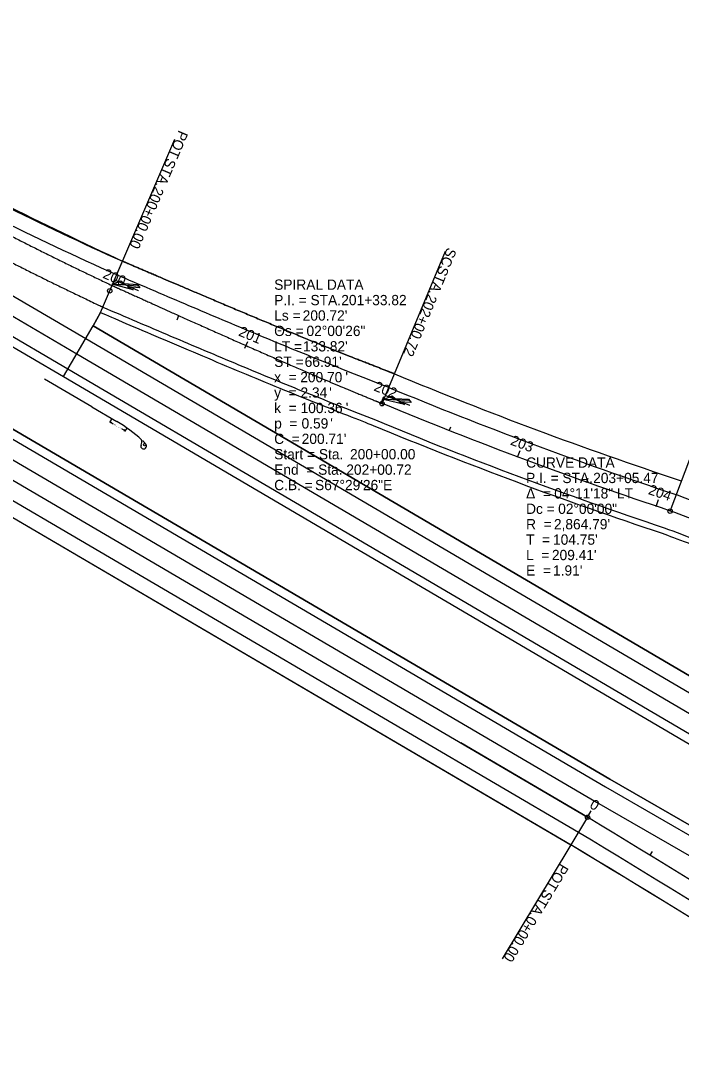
# Model space of a CAD drawing. Extents: x 76539 to 88870, y 518807 to 527554.
# Drawn here: x 85984 to 86434, y 523086 to 523783 of the extents above; entities that cross this region are included whole.
import ezdxf

# ---------------------------------------------------------------- set-up
doc = ezdxf.new("R2010")
doc.units = 0
for name, color, linetype in [('Default', 7, 'Continuous'), ('GE_P_Alignment_100_Cardinal_Points', 7, 'Continuous'), ('GE_P_Alignment_100_Curve_Data', 7, 'Continuous'), ('GE_P_Alignment_100_Stations', 7, 'Continuous'), ('PM_P_Cells', 7, 'Continuous'), ('PM_P_Channelizing_Line', 7, 'Continuous'), ('PM_P_Dotted_Line', 7, 'Continuous'), ('PM_P_Edge_Line', 7, 'Continuous'), ('PM_P_Lane_Line', 7, 'Continuous'), ('PV_P_Shoulder', 7, 'Continuous'), ('RD_P_GR_Lt', 7, 'Continuous'), ('RD_P_GR_Rt', 7, 'Continuous'), ('SC_Scratch1', 7, 'Continuous'), ('XS_P_Pavt_Surface', 7, 'Continuous')]:
    doc.layers.add(name, color=color, linetype=linetype)

msp = doc.modelspace()

# ---------------------------------------------------------------- linework, layer by layer
at = {"layer": 'Default'}
for points, degree in [([(86053.64, 523619.35), (86062.12, 523615.72), (86093.34, 523602.34), (86145.72, 523580.15), (86198.2, 523558.5), (86229.8, 523546.18), (86238.39, 523542.79)], 2), ([(86049.7, 523610.16), (86065.07, 523603.58), (86095.79, 523590.43), (86141.94, 523570.92), (86188.18, 523551.78), (86219.22, 523539.58), (86234.73, 523533.48)], 3), ([(86038.68, 523584.42), (86047.19, 523580.78), (86078.53, 523567.34), (86131.15, 523545.05), (86184, 523523.25), (86215.78, 523510.87), (86224.39, 523507.46)], 3), ([(86430.77, 523460.3), (86446.36, 523454.43), (86477.52, 523442.7), (86524.32, 523425.33), (86571.2, 523408.33), (86602.64, 523397.56), (86618.35, 523392.18)], 3), ([(86426.66, 523449.38), (86442.25, 523443.51), (86473.45, 523431.77), (86520.32, 523414.37), (86567.33, 523397.33), (86598.86, 523386.52), (86614.62, 523381.12)], 3), ([(86421.2, 523433.99), (86429.83, 523430.74), (86461.56, 523418.78), (86514.82, 523398.96), (86568.35, 523379.62), (86600.51, 523368.71), (86609.22, 523365.71)], 3)]:
    msp.add_open_spline(points, degree=degree, dxfattribs=at)
at = {"layer": 'GE_P_Alignment_100_Cardinal_Points'}
for p, q in [((86044.98, 523599.13), (86089.26, 523702.55)), ((86230.4, 523522.29), (86273.56, 523626.18)), ((86426.54, 523449.07), (86466.17, 523554.36)), ((86370.31, 523240.55), (86312.24, 523144.2))]:
    msp.add_line(p, q, dxfattribs=at)
for centre in [(86044.98, 523599.13), (86230.4, 523522.29), (86426.54, 523449.07), (86370.31, 523240.55)]:
    msp.add_circle(centre, 1.5, dxfattribs=at)
at = {"layer": 'GE_P_Alignment_100_Stations'}
for p, q in [((86044.98, 523599.13), (86046.95, 523603.73)), ((86090.96, 523579.48), (86092.13, 523582.24)), ((86137.02, 523560.04), (86138.95, 523564.65)), ((86183.25, 523540.99), (86184.38, 523543.77)), ((86229.72, 523522.55), (86231.53, 523527.21)), ((86276.06, 523503.77), (86277.17, 523506.56)), ((86322.72, 523485.79), (86324.47, 523490.47)), ((86369.68, 523468.63), (86370.68, 523471.45)), ((86416.93, 523452.28), (86418.52, 523457.02)), ((86370.31, 523240.55), (86372.89, 523244.84)), ((86413.06, 523214.62), (86414.62, 523217.19))]:
    msp.add_line(p, q, dxfattribs=at)
at = {"layer": 'PM_P_Cells'}
for p, q in [((86046.68, 523603.73), (86052.62, 523606.03)), ((86061, 523599.77), (86046.68, 523603.73)), ((86064.05, 523602.43), (86047.22, 523603.69)), ((86047.95, 523606.53), (86047.95, 523606.53)), ((86064.5, 523599.06), (86047.95, 523606.53)), ((86052.62, 523606.03), (86054.79, 523604.18)), ((86054.79, 523604.18), (86063.8, 523603.48)), ((86063.8, 523603.48), (86065.45, 523601.18)), ((86055.64, 523603.06), (86055.64, 523603.06)), ((86065.45, 523601.18), (86057.15, 523601.83)), ((86057.15, 523601.83), (86061, 523599.77)), ((86064.5, 523599.06), (86064.5, 523599.06)), ((86231.34, 523525.07), (86237.19, 523527.57)), ((86232.5, 523527.91), (86232.5, 523527.91)), ((86249.3, 523521.01), (86232.5, 523527.91)), ((86237.19, 523527.57), (86239.42, 523525.8)), ((86245.78, 523521.6), (86231.34, 523525.07)), ((86248.74, 523524.36), (86231.88, 523525.05)), ((86239.42, 523525.8), (86248.45, 523525.4)), ((86240.31, 523524.7), (86240.31, 523524.7)), ((86250.18, 523523.16), (86241.86, 523523.53)), ((86241.86, 523523.53), (86245.78, 523521.6)), ((86248.45, 523525.4), (86250.18, 523523.16)), ((86249.3, 523521.01), (86249.3, 523521.01))]:
    msp.add_line(p, q, dxfattribs=at)
at = {"layer": 'PM_P_Channelizing_Line'}
for p, q in [((85682.48, 523769.61), (86028.63, 523566.62)), ((86039.58, 523588.4), (86039.64, 523588.38)), ((86039.64, 523588.38), (86039.97, 523588.23)), ((86370.31, 523240.55), (86284.05, 523291.16))]:
    msp.add_line(p, q, dxfattribs=at)
msp.add_arc((81834.27, 515713.3), 8788.35, 54.569749, 58.926203, dxfattribs=at)
for points, degree in [([(85874.65, 523673.93), (85876.18, 523673.07), (85881.46, 523670.08), (85891.13, 523664.67), (85898.83, 523660.4), (85907.09, 523655.86), (85915.22, 523651.42), (85923.41, 523647), (85931.61, 523642.62), (85939.82, 523638.26), (85948.05, 523633.93), (85956.29, 523629.64), (85964.55, 523625.37), (85972.83, 523621.14), (85981.12, 523616.94), (85989.43, 523612.77), (85997.76, 523608.62), (86006.06, 523604.53), (86014.54, 523600.39), (86022.46, 523596.56), (86032.5, 523591.75), (86038, 523589.15), (86039.58, 523588.4)], 3), ([(86039.97, 523588.23), (86039.99, 523588.22), (86040.04, 523588.19), (86040.18, 523588.13), (86040.23, 523588.11), (86040.25, 523588.1)], 2)]:
    msp.add_open_spline(points, degree=degree, dxfattribs=at)
at = {"layer": 'PM_P_Dotted_Line'}
for p, q in [((84442.53, 524371.56), (86370.31, 523240.55)), ((86230.2, 523522.41), (86230.4, 523522.31)), ((86230.35, 523522.34), (86230.52, 523522.27))]:
    msp.add_line(p, q, dxfattribs=at)
for points, degree in [([(85882.47, 523687.88), (85885.15, 523686.36), (85890.51, 523683.33), (85898.56, 523678.82), (85906.63, 523674.35), (85914.72, 523669.9), (85922.83, 523665.48), (85930.95, 523661.09), (85939.1, 523656.73), (85947.25, 523652.4), (85955.43, 523648.1), (85963.62, 523643.84), (85971.83, 523639.6), (85980.05, 523635.39), (85988.29, 523631.21), (85996.55, 523627.07), (86004.82, 523622.95), (86013.11, 523618.87), (86021.41, 523614.81), (86029.73, 523610.79), (86038.06, 523606.79), (86043.63, 523604.16), (86046.42, 523602.84)], 3), ([(86046.54, 523602.78), (86054.95, 523598.99), (86085.93, 523584.97), (86137.96, 523561.72), (86190.34, 523538.89), (86221.85, 523525.9), (86230.35, 523522.34)], 2), ([(86230.4, 523522.31), (86230.42, 523522.31), (86230.46, 523522.29), (86230.52, 523522.26), (86230.57, 523522.24), (86230.63, 523522.21), (86230.69, 523522.19), (86230.74, 523522.16), (86230.8, 523522.14), (86230.86, 523522.12), (86230.91, 523522.09), (86230.97, 523522.07), (86231.03, 523522.04), (86231.08, 523522.02), (86231.14, 523521.99), (86231.2, 523521.97), (86231.25, 523521.94), (86231.31, 523521.92), (86231.37, 523521.89), (86231.42, 523521.87), (86231.48, 523521.84), (86231.52, 523521.83), (86231.54, 523521.82)], 3)]:
    msp.add_open_spline(points, degree=degree, dxfattribs=at)
at = {"layer": 'PM_P_Edge_Line'}
for p, q in [((84485.07, 524443.99), (86016.49, 523545.92)), ((84454.69, 524392.25), (86382.45, 523261.25)), ((84522.68, 524310.56), (86364.11, 523230.28)), ((86028.65, 523566.61), (87281.21, 522830.81)), ((86016.49, 523545.92), (87269.05, 522810.12)), ((86234.73, 523533.48), (86234.9, 523533.41)), ((86234.73, 523533.48), (86234.9, 523533.41)), ((86234.9, 523533.41), (86235, 523533.37)), ((86234.9, 523533.41), (86235, 523533.37)), ((86430.32, 523460.46), (86430.54, 523460.39)), ((86430.32, 523460.46), (86430.54, 523460.39)), ((86430.54, 523460.39), (86430.77, 523460.3)), ((86430.54, 523460.39), (86430.77, 523460.3)), ((86382.45, 523261.25), (86660.77, 523100.7))]:
    msp.add_line(p, q, dxfattribs=at)
for centre, radius, start, end in [((87059.11, 525861.34), 2467.13, 241.57045, 245.84895), ((87329.68, 526167.78), 2852.79, 247.43551, 251.62371), ((87329.68, 526167.78), 2852.79, 247.43551, 251.62371), ((87329.68, 526167.78), 2876.79, 247.43766, 251.61901), ((81834.27, 515713.3), 8776.35, 54.569749, 58.926203)]:
    msp.add_arc(centre, radius, start, end, dxfattribs=at)
for points in [[(86049.7, 523610.16), (86065.07, 523603.58), (86095.79, 523590.43), (86141.94, 523570.92), (86188.18, 523551.78), (86219.22, 523539.58), (86234.73, 523533.48)], [(86040.25, 523588.1), (86055.64, 523581.51), (86086.42, 523568.33), (86132.72, 523548.76), (86179.15, 523529.54), (86210.32, 523517.29), (86225.89, 523511.17)], [(86430.77, 523460.3), (86446.36, 523454.43), (86477.52, 523442.7), (86524.32, 523425.33), (86571.2, 523408.33), (86602.64, 523397.56), (86618.35, 523392.18)], [(86422.53, 523437.76), (86438.06, 523431.91), (86469.22, 523420.18), (86516.1, 523402.79), (86563.18, 523385.71), (86594.77, 523374.89), (86610.54, 523369.48)]]:
    msp.add_open_spline(points, degree=3, dxfattribs=at)
at = {"layer": 'PM_P_Lane_Line'}
for p, q in [((84491.14, 524454.34), (86022.56, 523556.27)), ((84448.61, 524381.9), (86376.38, 523250.9)), ((86022.57, 523556.26), (87275.13, 522820.47)), ((86426.64, 523449.39), (86426.65, 523449.39)), ((86426.65, 523449.39), (86426.66, 523449.38)), ((86376.45, 523250.86), (86654.78, 523090.3))]:
    msp.add_line(p, q, dxfattribs=at)
msp.add_arc((87329.68, 526167.78), 2864.46, 247.43551, 251.62371, dxfattribs=at)
at = {"layer": 'PV_P_Shoulder'}
for p, q in [((84482.04, 524438.81), (86013.45, 523540.74)), ((84457.73, 524397.42), (86385.49, 523266.43)), ((84517.62, 524301.93), (86359.05, 523221.65)), ((86038.68, 523584.42), (86033.71, 523575.23)), ((86033.71, 523575.23), (87286.27, 522839.43)), ((86013.45, 523540.74), (87266.01, 522804.95)), ((86238.39, 523542.79), (86238.65, 523542.69)), ((86238.65, 523542.69), (86238.84, 523542.61)), ((86433.47, 523469.95), (86433.88, 523469.81)), ((86433.88, 523469.81), (86434.29, 523469.66)), ((86385.49, 523266.43), (86663.82, 523105.87))]:
    msp.add_line(p, q, dxfattribs=at)
for centre, radius, start, end in [((87059.11, 525861.34), 2457.13, 241.57045, 245.84895), ((87329.68, 526167.78), 2842.79, 247.43551, 251.62371), ((87329.68, 526167.78), 2880.79, 247.43834, 251.61746), ((81834.27, 515713.3), 8766.35, 54.569749, 58.926203)]:
    msp.add_arc(centre, radius, start, end, dxfattribs=at)
at = {"layer": 'RD_P_GR_Lt'}
msp.add_line((86032.87, 523520.05), (86000.54, 523539.05), dxfattribs=at)
at = {"layer": 'RD_P_GR_Rt'}
msp.add_line((86032.87, 523520.05), (86049.89, 523510.05), dxfattribs=at)
msp.add_circle((86068.77, 523494.43), 0.79, dxfattribs=at)
msp.add_arc((85998.98, 523423.4), 100.51, 47.6605, 59.5655, dxfattribs=at)
for centre, major_axis, start_param, end_param in [((86068.07, 523493.37), (-0.89, -1.78), 4.797576, 8.898127), ((86061.38, 523496.1), (2.53, 5.11), 4.770091, 5.435472), ((86061.34, 523488.6), (4.61, 9.29), 5.763289, 6.120658)]:
    msp.add_ellipse(centre, major_axis=major_axis, ratio=0.944544, start_param=start_param, end_param=end_param, dxfattribs=at)
at = {"layer": 'SC_Scratch1'}
for p, q in [((86046.34, 523512.14), (86044.77, 523509.46)), ((86045.05, 523509.95), (86046.06, 523509.6)), ((86045.85, 523509.24), (86045.05, 523509.95)), ((86046.06, 523509.6), (86045.85, 523509.24)), ((86045.96, 523509.42), (86047.45, 523508.54)), ((86055.38, 523503.3), (86056.93, 523505.51)), ((86054.76, 523504.24), (86053.49, 523504.99)), ((86054.87, 523504.42), (86054.66, 523504.06)), ((86054.66, 523504.06), (86055.67, 523503.71)), ((86055.67, 523503.71), (86054.87, 523504.42))]:
    msp.add_line(p, q, dxfattribs=at)
at = {"layer": 'XS_P_Pavt_Surface'}
for p, q in [((84482.04, 524438.81), (86013.45, 523540.74)), ((86385.49, 523266.43), (84457.73, 524397.42)), ((84517.62, 524301.93), (86359, 523221.68)), ((86038.68, 523584.42), (86053.64, 523619.35)), ((86033.71, 523575.23), (86038.68, 523584.42)), ((86013.48, 523540.73), (86033.71, 523575.23)), ((87286.27, 522839.43), (86033.71, 523575.23)), ((86013.45, 523540.74), (87266.01, 522804.95)), ((86663.82, 523105.87), (86385.49, 523266.43))]:
    msp.add_line(p, q, dxfattribs=at)
for centre, radius, start, end in [((87945.87, 527657.07), 4459.09, 242.53314, 244.90495), ((87329.68, 526167.78), 2842.79, 247.43551, 251.62371), ((87329.68, 526167.78), 2880.79, 247.43834, 251.61746), ((81834.27, 515713.3), 8766.35, 54.568901, 58.925818)]:
    msp.add_arc(centre, radius, start, end, dxfattribs=at)
for points, degree in [([(86238.39, 523542.79), (86229.8, 523546.18), (86198.2, 523558.5), (86145.72, 523580.15), (86093.34, 523602.34), (86062.12, 523615.72), (86053.64, 523619.35)], 2), ([(86038.68, 523584.42), (86047.19, 523580.78), (86078.53, 523567.34), (86131.15, 523545.05), (86184, 523523.25), (86215.78, 523510.87), (86224.39, 523507.46)], 3), ([(86421.2, 523433.99), (86429.83, 523430.74), (86461.56, 523418.78), (86514.82, 523398.96), (86568.35, 523379.62), (86600.51, 523368.71), (86609.22, 523365.71)], 3)]:
    msp.add_open_spline(points, degree=degree, dxfattribs=at)

# ---------------------------------------------------------------- texts
at = {"layer": 'GE_P_Alignment_100_Cardinal_Points'}
for s, rotation, p in [('POT', 246.82138, (86092.11, 523708.94)), (' STA. ', 246.82138, (86085.02, 523692.39)), ('200+00.00', 246.82138, (86075.72, 523670.67)), ('SC', 247.43551, (86274.89, 523629.1)), (' STA. ', 247.43551, (86270.76, 523619.17)), ('202+00.72', 247.43551, (86261.7, 523597.35)), ('POT', 238.9262, (86351.77, 523209.59)), (' STA. ', 238.9262, (86342.48, 523194.17)), ('0+00.00', 238.9262, (86330.28, 523173.93))]:
    msp.add_text(s, height=7, rotation=rotation, dxfattribs=at).set_placement(p)
at = {"layer": 'GE_P_Alignment_100_Curve_Data'}
for s, p in [('SPIRAL DATA', (86156.96, 523599.85)), ('P.I. = STA. ', (86156.96, 523589.35)), ('201+33.82', (86202.63, 523589.35)), ('Ls = ', (86156.96, 523578.85)), ("200.72'", (86176.37, 523578.85)), ('Θs = ', (86156.96, 523568.35)), ('02°00\'26"', (86178.97, 523568.35)), ('LT = ', (86156.96, 523557.85)), ("133.82'", (86176.6, 523557.85)), ('ST = ', (86156.96, 523547.35)), ("66.91'", (86177.73, 523547.35)), ('x  = ', (86156.96, 523536.85)), ('200.70', (86174.71, 523536.85)), ("'", (86205.43, 523536.85)), ('2.34', (86174.87, 523526.35)), ("'", (86194.41, 523526.35)), ('y  = ', (86156.96, 523526.35)), ('k  = ', (86156.96, 523515.85)), ('100.36', (86174.95, 523515.85)), ("'", (86205.67, 523515.85)), ('0.59', (86175.6, 523505.35)), ('p  = ', (86156.96, 523505.35)), ("'", (86195.15, 523505.35)), ('C  = ', (86156.96, 523494.85)), ("200.71'", (86175.7, 523494.85)), ('Start = Sta. ', (86156.96, 523484.35)), ('200+00.00', (86208.6, 523484.35)), ('CURVE DATA', (86328.47, 523478.68)), ('End  = Sta. ', (86156.96, 523473.85)), ('202+00.72', (86206.05, 523473.85)), ('P.I. = STA. ', (86328.47, 523468.18)), ('203+05.47', (86374.13, 523468.18)), ('C.B. = ', (86156.96, 523463.35)), ('S67°29\'26"E', (86184.78, 523463.35)), ('Δ  = ', (86328.47, 523457.68)), ('04°11\'18" LT', (86347.66, 523457.68)), ('Dc = ', (86328.47, 523447.18)), ('02°00\'00"', (86350.31, 523447.18)), ('R  = ', (86328.47, 523436.68)), ("2,864.79'", (86347.42, 523436.68)), ('T  = ', (86328.47, 523426.18)), ("104.75'", (86346.81, 523426.18)), ('L  = ', (86328.47, 523415.68)), ("209.41'", (86346.07, 523415.68)), ('E  = ', (86328.47, 523405.18)), ("1.91'", (86346.82, 523405.18))]:
    msp.add_text(s, height=7, dxfattribs=at).set_placement(p)
at = {"layer": 'GE_P_Alignment_100_Stations'}
for s, rotation, p in [('200', 336.82138, (86039.75, 523608.17)), ('201', 337.31959, (86132.16, 523568.84)), ('202', 338.81421, (86224.34, 523531.34)), ('203', 339.42111, (86317.26, 523494.52)), ('204', 341.42111, (86411.17, 523460.81)), ('0', 328.9262, (86371.15, 523247.34))]:
    msp.add_text(s, height=7, rotation=rotation, dxfattribs=at).set_placement(p)
at = {"layer": 'SC_Scratch1'}
msp.add_text('LENGTH OF NEED', height=0.5506, rotation=149.56844, dxfattribs=at).set_placement((86053.45, 523505.3))

doc.saveas('drawing.dxf')
